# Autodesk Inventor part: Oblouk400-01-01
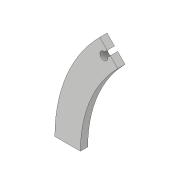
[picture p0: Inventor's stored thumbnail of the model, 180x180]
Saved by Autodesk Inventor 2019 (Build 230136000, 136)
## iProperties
Created: 2019-05
Part Number: Oblouk400-01-01
Material: Všeobecné
Document SubType Name: Modeling
Density: 1 g/cm^3
Appearance: Výchozí
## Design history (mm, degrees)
sketch "Náčrt1"
  geometry: L1 (0, 123.688)-(0, -20.615) reference; L2 (-179.815, 0)-(29.969, 0) reference; L3 (-141.421, 141.421)-(0, 0); L4 (-240, 0)-(-200, 0); L5 (-161.978, 154.098)-(-158.038, 158.038); L6 (-153.089, 153.089)-(-157.029, 149.149); L7 (-163.165, 147.962)-(-155.563, 155.563); L8 (-141.421, 141.421)-(-153.089, 153.089); L9 (-158.038, 158.038)-(-169.706, 169.706); L10 (-158.038, 158.038)-(-153.089, 153.089); A1 r 200 centre (0, 0) between (-141.421, 141.421) and (-200, 0); A2 r 240 centre (0, 0) between (-169.706, 169.706) and (-240, 0); A3 r 6.25 centre (-163.165, 147.962) between (-161.978, 154.098) and (-157.029, 149.149); 1 further point
  constraints: 16 end point, 6 point on circle, 3 centre point, 3 collinear, 2 equal length, 1 coincident, 1 midpoint, 1 parallel, 1 point on line, 1 other
  dimensions: "d0" = 400 diameter of A1; "d2" = 40 distance of L4.end L4.start; "d12" = 45 deg angle of L2 L3; "d61" = 12.5 diameter of A3; "d62" = 7 distance between parallel lines of L5 L6; "d67" = 17.00005 dimension on A3 L8
extrude "Oblouk1" new body sketch "Náčrt1" stored distance "d22" = 11.5; taper "d23" = 0 deg
node "Těleso2"
